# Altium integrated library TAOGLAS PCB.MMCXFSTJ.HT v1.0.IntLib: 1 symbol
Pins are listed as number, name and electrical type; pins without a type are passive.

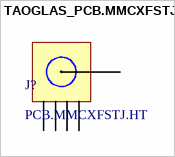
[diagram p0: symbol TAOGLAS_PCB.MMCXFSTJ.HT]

## TAOGLAS_PCB.MMCXFSTJ.HT
designator J?, comment PCB.MMCXFSTJ.HT
MMCX(F) Jack – Vertical PCB Through Hole Jack; ComponentLibStatus: Created; MFG: Taoglas; Temp_High: +85C; Temp_Low: -40C
footprint TAOGLAS_PCB.MMCXFSTJ.HT (MMCX(F) Jack – Vertical PCB Through Hole Jack)
pins: 1 RF, 2 GND, 3 GND, 4 GND, 5 GND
